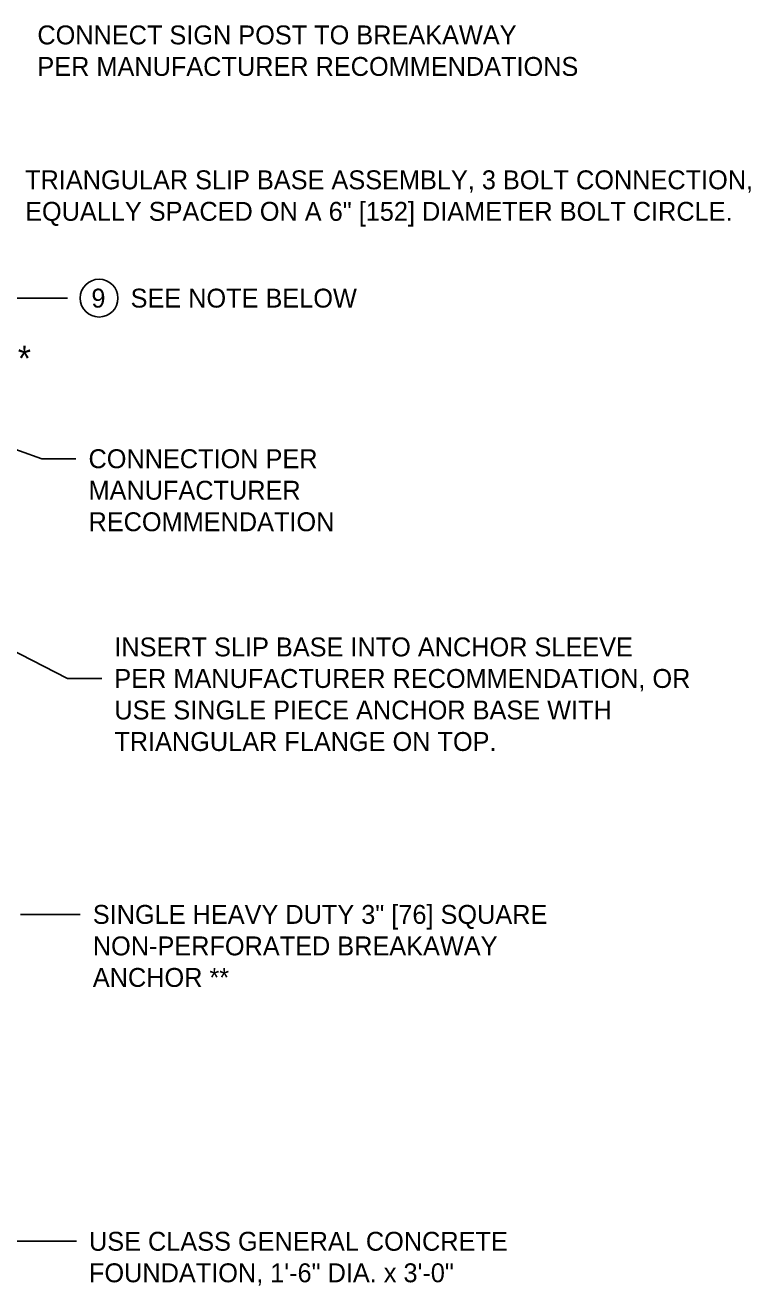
# Model space of a CAD drawing. Extents: x 49940 to 50043, y 49986 to 50011.
# Drawn here: x 50007.993 to 50010.295, y 49992.567 to 49996.567 of the extents above; entities that cross this region are included whole.
import ezdxf

# ---------------------------------------------------------------- set-up
doc = ezdxf.new("R2010")
doc.units = 0
doc.layers.add('Level 2', color=7, linetype='Continuous')
doc.layers.add('Level 3', color=7, linetype='Continuous')

msp = doc.modelspace()

# ---------------------------------------------------------------- linework, layer by layer
at = {"layer": 'Level 2'}
msp.add_circle((50008.2273, 49995.701), 0.06, dxfattribs=at)
at = {"layer": 'Level 3'}
for p, q in [((50007.5059, 49995.701), (50008.1273, 49995.701)), ((50007.382, 49995.4248), (50008.0456, 49995.1914)), ((50008.0456, 49995.1914), (50008.1538, 49995.1914)), ((50007.2703, 49994.9333), (50008.1275, 49994.4941)), ((50008.1275, 49994.4941), (50008.2357, 49994.4941)), ((50007.9781, 49993.7454), (50008.1675, 49993.7454)), ((50007.9062, 49992.7081), (50008.1553, 49992.7081))]:
    msp.add_line(p, q, dxfattribs=at)

# ---------------------------------------------------------------- texts
at = {"layer": 'Level 2'}
for s, p in [('CONNECT SIGN POST TO BREAKAWAY ', (50008.0316, 49996.5062)), ('PER MANUFACTURER RECOMMENDATIONS', (50008.0316, 49996.4062)), ('TRIANGULAR SLIP BASE ASSEMBLY, 3 BOLT CONNECTION, ', (50007.9926, 49996.0464)), ('EQUALLY SPACED ON A 6" [152] DIAMETER BOLT CIRCLE. ', (50007.9926, 49995.9464)), ('9', (50008.2029, 49995.671)), ('SEE NOTE BELOW', (50008.3273, 49995.671)), ('CONNECTION PER ', (50008.1938, 49995.1614)), ('MANUFACTURER ', (50008.1938, 49995.0614)), ('RECOMMENDATION', (50008.1938, 49994.9614)), ('INSERT SLIP BASE INTO ANCHOR SLEEVE ', (50008.2757, 49994.5641)), ('PER MANUFACTURER RECOMMENDATION, OR', (50008.2757, 49994.4641)), ('USE SINGLE PIECE ANCHOR BASE WITH ', (50008.2757, 49994.3641)), ('TRIANGULAR FLANGE ON TOP. ', (50008.2757, 49994.2641)), ('SINGLE HEAVY DUTY 3" [76] SQUARE', (50008.2075, 49993.7154)), ('NON-PERFORATED BREAKAWAY', (50008.2075, 49993.6154)), ('ANCHOR **', (50008.2075, 49993.5154)), ('USE CLASS GENERAL CONCRETE', (50008.1953, 49992.6781)), ('FOUNDATION, 1\'-6" DIA. x 3\'-0"', (50008.1953, 49992.5781))]:
    msp.add_text(s, height=0.06, dxfattribs=at).set_placement(p)
msp.add_text('*', height=0.08, rotation=359.5, dxfattribs=at).set_placement((50007.9691, 49995.4701))

doc.saveas('drawing.dxf')
